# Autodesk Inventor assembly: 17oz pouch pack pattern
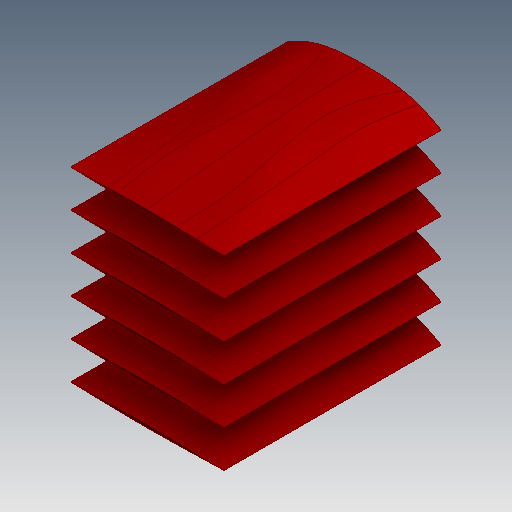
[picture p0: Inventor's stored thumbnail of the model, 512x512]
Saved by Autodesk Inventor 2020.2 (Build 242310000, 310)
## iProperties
Created: 1999-11
Part Number: 17oz pouch pack pattern
Document SubType Name: Assembly
Designer: glanglot
Control State: 0
Checked Out: False
Last Check In By: glanglot
Last Check In Date: 1999-12-14
Master: False
Shininess: 0.0
Length Units: 11269
Angle Units: 11279
Time Units: 11290
Mass Units: 11283
Length Display Precision: 3
Angle Display Precision: 2
Compacted: True
Dimensions: 222x215,9x152,4 mm
Mass: 0 kg
DocNumber: 17oz pouch pack pattern.iam
Folder: 01 - Themengebiete\Simplification\01 - Packaging machine\
VDS_Category: 3D Komponenten
Density: 0.0
Volumn: 0.0
Area: 0.0
PropertySet Name: Model Information
Author: glanglot
Revision Number: -
Title: products
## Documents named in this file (2)
- D:\07 - DEMODATEN\OTX 2019 - Dataset - UPDATE - Dez2019\Designs\07-Packing machine\17oz pouch pack pattern.iam
- D:\07 - DEMODATEN\OTX 2019 - Dataset - UPDATE - Dez2019\Designs\07-Packing machine\Parts\ADSK-011830.ipt
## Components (6 placed, 1 different names)
1. ADSK-011830:1 — Fluchtend:1, Fluchtend:2, Fluchtend:3
2. ADSK-011830:2
3. ADSK-011830:3
4. ADSK-011830:4
5. ADSK-011830:5
6. ADSK-011830:6
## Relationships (3: Flush 3)
- Fluchtend:1 [Flush]: ADSK-011830:1
- Fluchtend:2 [Flush]: ADSK-011830:1
- Fluchtend:3 [Flush]: ADSK-011830:1
